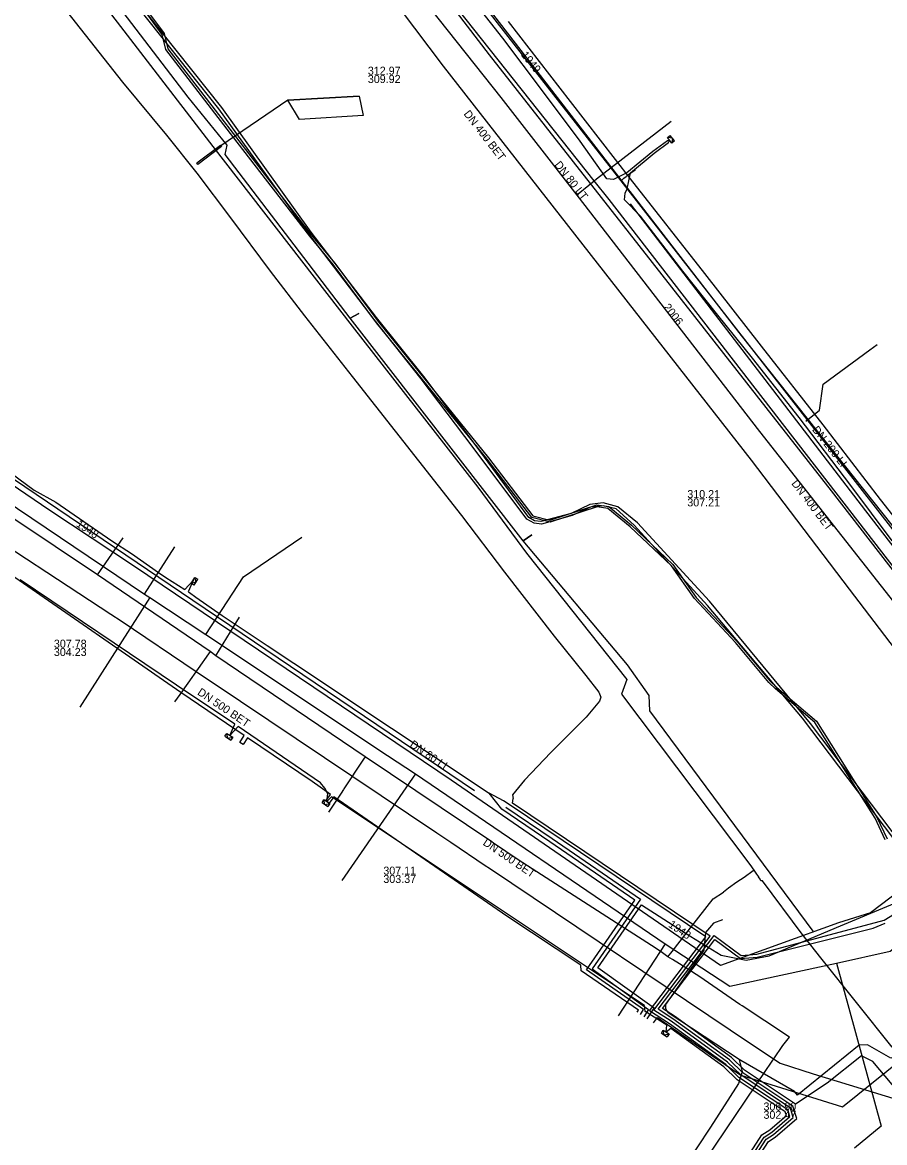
# Model space of a CAD drawing. Extents: x -600391 to -599491, y -1160176 to -1159402.
# Drawn here: x -600328.5 to -600242.3, y -1160119 to -1160007 of the extents above; entities that cross this region are included whole.
import ezdxf

# ---------------------------------------------------------------- set-up
doc = ezdxf.new("R2010")
doc.units = 0
for name, color, linetype in [('31', 7, 'Continuous'), ('CETIN_linie', 7, 'Continuous'), ('Vrstva 1', 7, 'Continuous'), ('Vrstva 12', 7, 'Continuous'), ('Vrstva 13', 7, 'Continuous'), ('Vrstva 15', 7, 'Continuous'), ('Vrstva 16', 7, 'Continuous'), ('Vrstva 19', 7, 'Continuous'), ('Vrstva 3', 7, 'Continuous'), ('Vrstva 42', 7, 'Continuous'), ('Vrstva 43', 7, 'Continuous'), ('Vrstva 44', 7, 'Continuous'), ('Vrstva 55', 7, 'Continuous'), ('Vrstva 58', 7, 'Continuous'), ('Vrstva 9', 7, 'Continuous')]:
    doc.layers.add(name, color=color, linetype=linetype)

# ---------------------------------------------------------------- blocks, each defined once
blk = doc.blocks.new('NN630')
at = {"layer": '31'}
for points in [[(0, -0.7), (-0.7, 0)], [(-0.7, -0.7), (-0.7, 0), (0.7, 0), (0.7, -0.7)], [(-0.7, -0.7), (0.7, -0.7)], [(0, -0.7), (0.7, 0)]]:
    blk.add_lwpolyline(points, dxfattribs=at)

msp = doc.modelspace()

# ---------------------------------------------------------------- linework, layer by layer
at = {"layer": 'CETIN_linie'}
for p, q in [((-600259.44, -1160097.05), (-600260.25, -1160097.98)), ((-600258.55, -1160096.72), (-600259.44, -1160097.05))]:
    msp.add_line(p, q, dxfattribs=at)
for points in [[(-600267.76, -1160025.17), (-600244.25, -1160055.86), (-600225.67, -1160079.89), (-600215.81, -1160092.29), (-600192.29, -1160121.78), (-600180.19, -1160137.43), (-600168.62, -1160151.9), (-600165.36, -1160149.31), (-600163.31, -1160147.71)], [(-600260.25, -1160097.98), (-600260.41, -1160099.75), (-600264.23, -1160105.17), (-600264.23, -1160105.56)], [(-600256.89, -1160110.66), (-600263.96, -1160106.02), (-600264.23, -1160105.56)], [(-600236.72, -1160106.71), (-600237.57, -1160107.73), (-600241.19, -1160110.36), (-600241.71, -1160110.53), (-600244.04, -1160109.21), (-600244.88, -1160109.24), (-600251.06, -1160114.23), (-600251.34, -1160113.88), (-600256.71, -1160110.78), (-600256.89, -1160110.66)], [(-600256.89, -1160110.66), (-600256.59, -1160111.91), (-600256.96, -1160113.06), (-600259.75, -1160117.44), (-600266.58, -1160127.77), (-600269.09, -1160131.27), (-600278.95, -1160145.57)]]:
    msp.add_lwpolyline(points, dxfattribs=at)
at = {"layer": 'Vrstva 1'}
msp.add_lwpolyline([(-600294.84, -1160014.4), (-600301.98, -1160014.81), (-600308.67, -1160019.36)], dxfattribs=at)
at = {"layer": 'Vrstva 13'}
for p, q in [((-600316.28, -1160064.17), (-600313.25, -1160059.45)), ((-600315.77, -1160064.51), (-600322.77, -1160075.48)), ((-600289.22, -1160082.13), (-600296.57, -1160092.79)), ((-600264.27, -1160099.11), (-600268.98, -1160106.3))]:
    msp.add_line(p, q, dxfattribs=at)
for points in [[(-600308.3, -1159974.75), (-600310.61, -1159976.58), (-600309.22, -1159978.29), (-600300.55, -1159989.29), (-600296.77, -1159994.11), (-600294.38, -1159997.18), (-600292.26, -1159999.96), (-600280.7, -1160014.54), (-600273.1, -1160024.31), (-600254.85, -1160047.91), (-600240.71, -1160065.87), (-600236.26, -1160071.52), (-600225.09, -1160085.97)], [(-600303.85, -1159981.9), (-600303.5, -1159982.35), (-600271.39, -1160022.87), (-600269.9, -1160024.72)], [(-600273.1, -1160024.31), (-600272.95, -1160024.18), (-600271.38, -1160022.88), (-600271.14, -1160022.68), (-600263.67, -1160016.9)], [(-600269.9, -1160024.72), (-600239.13, -1160064.49), (-600235.85, -1160068.55), (-600222.99, -1160084.95), (-600222.26, -1160085.9), (-600219.33, -1160089.71)], [(-600364.61, -1160031.76), (-600357.97, -1160036.11), (-600353.75, -1160038.9), (-600347.83, -1160042.83), (-600335.57, -1160051.15), (-600331.77, -1160053.74), (-600316.28, -1160064.17), (-600315.77, -1160064.51), (-600310.16, -1160068.2), (-600292.01, -1160080.31), (-600289.22, -1160082.13), (-600264.27, -1160099.11), (-600257.81, -1160103.36), (-600247.15, -1160101.04), (-600241.8, -1160099.85), (-600232.66, -1160092.61)], [(-600310.16, -1160068.2), (-600306.4, -1160062.44), (-600300.56, -1160058.49)], [(-600247.15, -1160101.04), (-600242.69, -1160117.34), (-600245.37, -1160119.54)]]:
    msp.add_lwpolyline(points, dxfattribs=at)
at = {"layer": 'Vrstva 16'}
for points in [[(-600149.13, -1160176.08), (-600149.77, -1160175.26), (-600153.28, -1160170.92), (-600160.82, -1160161.59), (-600162.37, -1160159.57), (-600191.81, -1160121.42), (-600215.03, -1160091.66), (-600218.37, -1160087.39), (-600241.27, -1160058.04), (-600268.45, -1160023.15), (-600268.66, -1160022.86), (-600279.96, -1160008.45), (-600285.15, -1160001.76), (-600292.76, -1159991.95), (-600306.26, -1159974.55), (-600310.89, -1159968.58), (-600323.17, -1159952.95), (-600331.19, -1159942.75), (-600331.3, -1159942.61), (-600336.91, -1159935.47), (-600352.95, -1159915.04), (-600356.32, -1159910.78), (-600372.09, -1159890.83), (-600376.45, -1159885.3)], [(-600268.66, -1160022.86), (-600268.4, -1160022.61), (-600268.17, -1160022.42), (-600268.03, -1160022.31), (-600267.38, -1160021.82), (-600267.25, -1160021.72)]]:
    msp.add_lwpolyline(points, dxfattribs=at)
at = {"layer": 'Vrstva 19'}
for points in [[(-600322.24, -1160002.78), (-600309.47, -1160019.44), (-600295.55, -1160037.38), (-600282.98, -1160053.47), (-600278.12, -1160060.08), (-600268.11, -1160072.71), (-600268.62, -1160074.16), (-600255.82, -1160091.2), (-600255.41, -1160091.75), (-600255.14, -1160092.15), (-600254.95, -1160092.41)], [(-600264.66, -1160099.92), (-600265.63, -1160099.29), (-600269.65, -1160096.7), (-600278.95, -1160090.72), (-600281.41, -1160089.05), (-600281.6, -1160088.93), (-600294.26, -1160080.42), (-600309.16, -1160070.33), (-600309.73, -1160069.9), (-600321, -1160062.23), (-600333.71, -1160053.74)], [(-600321, -1160062.23), (-600319.04, -1160059.41), (-600318.42, -1160058.53)], [(-600309.16, -1160070.33), (-600307.32, -1160067.35), (-600306.79, -1160066.48)], [(-600309.73, -1160069.9), (-600309.9, -1160070.15), (-600311.96, -1160073.06), (-600312.3, -1160073.54), (-600312.51, -1160073.83), (-600313.3, -1160074.94)], [(-600294.26, -1160080.42), (-600294.42, -1160080.67), (-600296.37, -1160083.63), (-600296.42, -1160083.7), (-600296.65, -1160084.05), (-600296.99, -1160084.56), (-600297.91, -1160085.96)], [(-600255.41, -1160091.75), (-600255.49, -1160091.82), (-600256.38, -1160092.5), (-600257.1, -1160092.95), (-600257.93, -1160093.55), (-600258.45, -1160093.95)], [(-600241.59, -1160109.43), (-600248.73, -1160100.51), (-600250.58, -1160098.14), (-600254.56, -1160092.81), (-600254.7, -1160092.81), (-600254.79, -1160092.65), (-600254.95, -1160092.41)], [(-600263.99, -1160100.4), (-600263.58, -1160099.89), (-600261.73, -1160097.53), (-600259.46, -1160094.61), (-600258.45, -1160093.95)], [(-600297.78, -1160176.08), (-600293.31, -1160169.25), (-600283.99, -1160155.21), (-600283.61, -1160154.66), (-600267.36, -1160131.31), (-600254.2, -1160111.77), (-600252.72, -1160109.58), (-600252.52, -1160109.29), (-600251.85, -1160108.43), (-600254.31, -1160106.81), (-600256.59, -1160105.32), (-600256.82, -1160105.17), (-600260.81, -1160102.41), (-600262.85, -1160101.12), (-600263.53, -1160100.69), (-600263.99, -1160100.4), (-600264.66, -1160099.92)]]:
    msp.add_lwpolyline(points, dxfattribs=at)
at = {"layer": 'Vrstva 3'}
for points in [[(-600301.98, -1160014.81), (-600294.84, -1160014.4), (-600294.45, -1160016.35), (-600300.8, -1160016.72)], [(-600308.71, -1160019.3), (-600308.61, -1160019.44), (-600310.95, -1160021.22), (-600311.05, -1160021.08)]]:
    msp.add_lwpolyline(points, close=True, dxfattribs=at)
at = {"layer": 'Vrstva 42'}
for points in [[(-600332.96, -1159994.69), (-600318.5, -1160013), (-600314.09, -1160018.29), (-600311.06, -1160022.09), (-600307.71, -1160026.57), (-600303.75, -1160031.89), (-600300.3, -1160036.37), (-600295.56, -1160042.43), (-600284.61, -1160056.3), (-600280.34, -1160061.97), (-600275.37, -1160068.38), (-600272.19, -1160072.29), (-600270.9, -1160073.95), (-600270.69, -1160074.46), (-600270.84, -1160074.85), (-600272.18, -1160076.46), (-600275.69, -1160080.01), (-600278.34, -1160082.75), (-600279.54, -1160084.22), (-600279.45, -1160084.58)], [(-600241.6, -1160058.84), (-600245.71, -1160053.3), (-600250.87, -1160046.53), (-600255.54, -1160040.6), (-600259.02, -1160036.3), (-600262.52, -1160031.88), (-600266.74, -1160026.4), (-600268.33, -1160024.76), (-600268.27, -1160024.1), (-600268.07, -1160023.66), (-600267.75, -1160022.06), (-600265.37, -1160020.11), (-600263.93, -1160019.02), (-600263.83, -1160018.82), (-600264.05, -1160018.86), (-600265.49, -1160019.95), (-600268.09, -1160022.08), (-600269.44, -1160022.72), (-600270.09, -1160022.66), (-600272.78, -1160018.91), (-600276.53, -1160013.86), (-600280.5, -1160008.62), (-600284.56, -1160003.42)], [(-600250.21, -1160046.88), (-600248.85, -1160045.8), (-600248.47, -1160043.19), (-600243.81, -1160039.74), (-600243.1, -1160039.22)], [(-600298.08, -1160084.9), (-600298.16, -1160084.84), (-600297.71, -1160084.18), (-600299.55, -1160082.9), (-600305.99, -1160078.53), (-600306.45, -1160079.21), (-600306.61, -1160079.09), (-600306.78, -1160078.98), (-600306.32, -1160078.3), (-600312.66, -1160073.99), (-600329.69, -1160062.21), (-600342.78, -1160053.6), (-600348.65, -1160049.55), (-600349.15, -1160050.28), (-600349.31, -1160050.17)], [(-600283.31, -1160083.83), (-600311.46, -1160064.8), (-600330.52, -1160051.9)], [(-600329.62, -1160052.08), (-600327.32, -1160053.77), (-600325.15, -1160054.99), (-600319.57, -1160058.84), (-600317.59, -1160060.11), (-600314.88, -1160062.02), (-600314.17, -1160062.49), (-600312.27, -1160063.71), (-600311.44, -1160062.8), (-600311.93, -1160063.93), (-600311.79, -1160064.02), (-600311.17, -1160064.46), (-600308.52, -1160066.29), (-600304.03, -1160069.31), (-600301.36, -1160071.08), (-600281.87, -1160084.07)], [(-600258.15, -1160123.69), (-600254.6, -1160118.21), (-600253.81, -1160117.7), (-600252.16, -1160116.27), (-600252.27, -1160115.91), (-600257.09, -1160112.69), (-600258.42, -1160111.4), (-600263.69, -1160107.56), (-600264.17, -1160107.93), (-600264.1, -1160107.25), (-600266.28, -1160105.89), (-600266.32, -1160105.27), (-600271.74, -1160101.67), (-600272.73, -1160101.02), (-600297.6, -1160084.43), (-600298.07, -1160084.89), (-600297.98, -1160084.12), (-600298.27, -1160083.56), (-600298.71, -1160083.01), (-600306.92, -1160077.38), (-600307.77, -1160078.28), (-600307.26, -1160077.16), (-600313.09, -1160073.25), (-600328.72, -1160062.73)], [(-600266.08, -1160106.62), (-600265.38, -1160105.56), (-600271.01, -1160101.52), (-600266.64, -1160095.21), (-600261.7, -1160098.39), (-600258.68, -1160100.26), (-600256.17, -1160100.74), (-600253.88, -1160100.31), (-600246.75, -1160097.3), (-600236.29, -1160092.95), (-600232.66, -1160090.29), (-600232.8, -1160088.04), (-600234.52, -1160085.09), (-600235.28, -1160084.08), (-600227.43, -1160078.19), (-600225.98, -1160079.93), (-600225.06, -1160079.23), (-600226.98, -1160076.75), (-600225.89, -1160075.9)], [(-600266.74, -1160106.18), (-600266.43, -1160105.69), (-600272.12, -1160101.71), (-600267.31, -1160094.76), (-600275.79, -1160088.92), (-600280.6, -1160085.65), (-600281.87, -1160084.07)], [(-600268.66, -1160155.89), (-600269.76, -1160157.39), (-600273.14, -1160155.2), (-600276.32, -1160152.95), (-600276.94, -1160149.72), (-600272.11, -1160143.22), (-600267.63, -1160136.53), (-600265.52, -1160132.58), (-600260.07, -1160124.97), (-600258.85, -1160124.83), (-600257.92, -1160123.88), (-600254.39, -1160118.42), (-600253.63, -1160117.94), (-600251.81, -1160116.37), (-600252.01, -1160115.72), (-600256.9, -1160112.46), (-600258.22, -1160111.17), (-600263.84, -1160107.1), (-600265.84, -1160105.81), (-600260.22, -1160098.41), (-600279.87, -1160085.2), (-600280.43, -1160084.83), (-600281.87, -1160084.07)], [(-600267.08, -1160105.96), (-600266.95, -1160105.74), (-600272.67, -1160101.81), (-600272.69, -1160101.24), (-600280.08, -1160096.35), (-600297.38, -1160084.41), (-600297.83, -1160085.07), (-600298.07, -1160084.89)], [(-600268.92, -1160155.74), (-600269.84, -1160156.94), (-600272.85, -1160155.05), (-600276.07, -1160152.73), (-600276.63, -1160149.79), (-600271.88, -1160143.3), (-600267.39, -1160136.65), (-600265.27, -1160132.73), (-600259.9, -1160125.25), (-600258.71, -1160125.11), (-600257.68, -1160124.07), (-600254.17, -1160118.64), (-600253.45, -1160118.18), (-600251.47, -1160116.47), (-600251.76, -1160115.53), (-600256.71, -1160112.22), (-600258.03, -1160110.94), (-600263.67, -1160106.85), (-600265.41, -1160105.73), (-600259.79, -1160098.34), (-600279.54, -1160085.06), (-600279.45, -1160084.58)], [(-600280.19, -1160085.46), (-600275.56, -1160088.59), (-600266.75, -1160094.66), (-600271.56, -1160101.62), (-600265.93, -1160105.67), (-600266.41, -1160106.4)], [(-600269.17, -1160155.57), (-600269.89, -1160156.57), (-600272.51, -1160154.84), (-600275.81, -1160152.56), (-600276.35, -1160149.83), (-600271.69, -1160143.42), (-600267.17, -1160136.78), (-600265.01, -1160132.89), (-600259.73, -1160125.54), (-600258.57, -1160125.4), (-600257.45, -1160124.26), (-600253.95, -1160118.86), (-600253.27, -1160118.42), (-600251.12, -1160116.57), (-600251.5, -1160115.34), (-600256.52, -1160111.99), (-600257.83, -1160110.71), (-600263.51, -1160106.6), (-600264.98, -1160105.66), (-600259.36, -1160098.27), (-600256.67, -1160100.27), (-600255.12, -1160100.16), (-600242.4, -1160096.76), (-600240.94, -1160095.86)], [(-600237.03, -1160118.61), (-600243.52, -1160110.86), (-600244.65, -1160110.3), (-600248.07, -1160113.03), (-600251.25, -1160115.15), (-600256.33, -1160111.75), (-600257.64, -1160110.48), (-600263.34, -1160106.35), (-600264.54, -1160105.58), (-600259.3, -1160098.68), (-600256.76, -1160100.58), (-600255.07, -1160100.45), (-600243.49, -1160097.56), (-600242.28, -1160097.04)], [(-600265.43, -1160107.02), (-600265.05, -1160106.47), (-600259.84, -1160110.1), (-600256.7, -1160112.24), (-600246.55, -1160115.41), (-600239.24, -1160109.52)]]:
    msp.add_lwpolyline(points, dxfattribs=at)
at = {"layer": 'Vrstva 44'}
for points in [[(-600238.73, -1160092.17), (-600250.56, -1160076.56), (-600260.04, -1160065.29), (-600267.37, -1160057.27), (-600269.17, -1160055.64), (-600270.47, -1160055.34), (-600271.74, -1160055.49), (-600273.55, -1160056.32), (-600276.64, -1160057.16), (-600277.35, -1160057.08), (-600278.1, -1160056.68), (-600283.45, -1160049.52), (-600288.66, -1160042.65), (-600293.36, -1160036.73), (-600299.88, -1160028.16), (-600308.86, -1160015.68), (-600317.75, -1160004.46)], [(-600238.5, -1160091.97), (-600249.74, -1160077.1), (-600259.84, -1160064.88), (-600267.05, -1160057.04), (-600269, -1160055.43), (-600270.47, -1160055.03), (-600271.8, -1160055.21), (-600273.67, -1160056.11), (-600276.68, -1160056.91), (-600277.32, -1160056.85), (-600277.91, -1160056.52), (-600283.15, -1160049.36), (-600288.37, -1160042.43), (-600293.1, -1160036.53), (-600299.63, -1160028.01), (-600308.56, -1160015.54), (-600317.55, -1160004.22)], [(-600316.21, -1160005.63), (-600314.34, -1160008.15), (-600313.96, -1160009.66), (-600306.88, -1160018.87), (-600299.64, -1160028.26), (-600297.28, -1160031.11), (-600292.94, -1160036.92), (-600281.91, -1160050.56), (-600277.48, -1160056.34), (-600275.78, -1160056.77), (-600271.09, -1160055.25), (-600269.91, -1160055.41), (-600267.63, -1160057.29), (-600263.5, -1160061.21), (-600261.19, -1160064.49), (-600257.1, -1160068.87), (-600253.77, -1160072.87), (-600253.12, -1160073.49), (-600249.16, -1160076.85), (-600243.13, -1160086.45), (-600242.1, -1160088.62)], [(-600242.28, -1160088.71), (-600243.3, -1160086.55), (-600249.31, -1160076.98), (-600253.25, -1160073.64), (-600253.92, -1160073.01), (-600257.25, -1160069), (-600261.34, -1160064.61), (-600263.65, -1160061.34), (-600267.76, -1160057.44), (-600270, -1160055.6), (-600271.07, -1160055.45), (-600275.77, -1160056.98), (-600277.59, -1160056.52), (-600282.07, -1160050.68), (-600293.1, -1160037.04), (-600297.44, -1160031.23), (-600299.79, -1160028.38), (-600307.04, -1160018.99), (-600314.15, -1160009.75), (-600314.53, -1160008.24), (-600316.34, -1160005.79)], [(-600236.37, -1160062.83), (-600242.76, -1160054.71), (-600248.48, -1160047.24), (-600254.65, -1160039.38), (-600260.32, -1160032.14), (-600267.72, -1160022.68), (-600273.74, -1160014.95), (-600279.94, -1160006.93)]]:
    msp.add_lwpolyline(points, dxfattribs=at)
at = {"layer": 'Vrstva 55'}
for points in [[(-600159.37, -1160161.02), (-600163.57, -1160162.94), (-600178.28, -1160142.93), (-600197.3, -1160118.52), (-600212.7, -1160098.72), (-600214.12, -1160096.9), (-600217.08, -1160091.68), (-600222.93, -1160082.91), (-600226.85, -1160080.74), (-600230.45, -1160076.02), (-600247.64, -1160053.85), (-600267.85, -1160028.08), (-600281.81, -1160010.27), (-600299.51, -1159987.18)], [(-600249.47, -1160097.84), (-600265.82, -1160075.82), (-600265.86, -1160074.3), (-600268.04, -1160071.24), (-600278.47, -1160058.84), (-600277.61, -1160058.25), (-600278.47, -1160058.83), (-600295.74, -1160036.59), (-600294.88, -1160036.12), (-600295.74, -1160036.58), (-600308.23, -1160020.23), (-600308.04, -1160019.31), (-600311.93, -1160014.51), (-600327.86, -1159993.65)], [(-600235.88, -1160090.06), (-600243.77, -1160096.03), (-600246.95, -1160097.03), (-600258.73, -1160101.28), (-600285.65, -1160082.77), (-600317.3, -1160061.42), (-600325.77, -1160055.81), (-600348.64, -1160040.24), (-600361.9, -1160031.37), (-600391.01, -1160011.45)]]:
    msp.add_lwpolyline(points, dxfattribs=at)
at = {"layer": 'Vrstva 58'}
msp.add_lwpolyline([(-600152.82, -1160155.25), (-600149.86, -1160159.29), (-600149.73, -1160159.86), (-600149.95, -1160160.27), (-600152.82, -1160162), (-600154.72, -1160162.87), (-600156.47, -1160162.91), (-600156.97, -1160162.77), (-600158.03, -1160162.46), (-600159.39, -1160161.61), (-600159.94, -1160160.91), (-600162.58, -1160157.66), (-600164.04, -1160155.63), (-600165.02, -1160154.82), (-600214.84, -1160091.44), (-600216.59, -1160090.02), (-600218.11, -1160088.27), (-600222.44, -1160082.52), (-600222.95, -1160080.77), (-600256.66, -1160038.32), (-600300.35, -1159981.75)], dxfattribs=at)
at = {"layer": 'Vrstva 9'}
msp.add_line((-600286.46, -1160011.41), (-600255.69, -1160050.79), dxfattribs=at)
for points in [[(-600311.58, -1159977.9), (-600310.56, -1159979.26), (-600292.17, -1160003.78), (-600286.46, -1160011.41)], [(-600353.65, -1160043.98), (-600349.35, -1160046.76), (-600338.57, -1160053.81), (-600334.52, -1160056.46), (-600319.67, -1160066.18), (-600318.62, -1160066.84)], [(-600255.69, -1160050.79), (-600245.87, -1160063.68), (-600231.33, -1160082.77), (-600225.57, -1160090.33)], [(-600318.62, -1160066.84), (-600311.13, -1160071.9), (-600309.1, -1160073.26), (-600308.63, -1160073.57), (-600306.71, -1160074.86), (-600287.09, -1160088.03), (-600285.68, -1160088.95)], [(-600285.68, -1160088.95), (-600282.24, -1160091.28), (-600281.84, -1160091.56), (-600255.55, -1160109.21), (-600255.54, -1160109.21), (-600252.77, -1160111.05)], [(-600252.77, -1160111.05), (-600249.47, -1160112.09), (-600241.09, -1160114.67), (-600228.62, -1160118.51)]]:
    msp.add_lwpolyline(points, dxfattribs=at)

# ---------------------------------------------------------------- block references
at = {"layer": 'Vrstva 43'}
for p, xscale, yscale, rotation in [((-600263.83, -1160018.82), 0.5, 0.5, 128), ((-600311.44, -1160062.8), 0.5, 0.5, 58.00000000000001), ((-600307.77, -1160078.28), 0.49999999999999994, 0.5000000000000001, -34.000000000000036), ((-600298.07, -1160084.89), 0.49999999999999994, 0.5000000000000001, -34.000000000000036), ((-600264.17, -1160107.93), 0.5, 0.5, -32.999999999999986)]:
    msp.add_blockref('NN630', p, dxfattribs=dict(at, xscale=xscale, yscale=yscale, rotation=rotation))

# ---------------------------------------------------------------- texts
at = {"layer": 'Vrstva 12'}
for s, p in [('312.97', (-600293.98, -1160012.26)), ('309.92', (-600293.98, -1160013.09)), ('310.21', (-600262.06, -1160054.57)), ('307.21', (-600262.06, -1160055.4)), ('307.78', (-600325.35, -1160069.52)), ('304.23', (-600325.35, -1160070.35)), ('307.11', (-600292.43, -1160092.2)), ('303.37', (-600292.43, -1160093.03)), ('306.90', (-600254.45, -1160115.77)), ('302.47', (-600254.45, -1160116.6))]:
    msp.add_text(s, height=0.8, dxfattribs=at).set_placement(p)
for s, rotation, p in [('DN 400 BET', 307.7929, (-600284.45, -1160016.19)), ('DN 400 BET', 307.2773, (-600251.7, -1160053.12)), ('DN 500 BET', 325.9716, (-600311.08, -1160074.15)), ('DN 500 BET', 325.788, (-600282.55, -1160089.17))]:
    msp.add_text(s, height=0.8, rotation=rotation, dxfattribs=at).set_placement(p)
at = {"layer": 'Vrstva 15'}
for s, rotation, p in [('1949', 308.3659, (-600278.72, -1160010.3)), ('DN 80 LT', 308.2513, (-600275.38, -1160021.28)), ('2006', 307.9075, (-600264.5, -1160035.51)), ('DN 200 LI', 308.1367, (-600249.63, -1160047.75)), ('1948', 326.0703, (-600323.19, -1160057.34)), ('DN 80 LI', 325.7838, (-600289.86, -1160079.37)), ('1948', 325.7838, (-600264.01, -1160097.37))]:
    msp.add_text(s, height=0.8, rotation=rotation, dxfattribs=at).set_placement(p)

doc.saveas('drawing.dxf')
